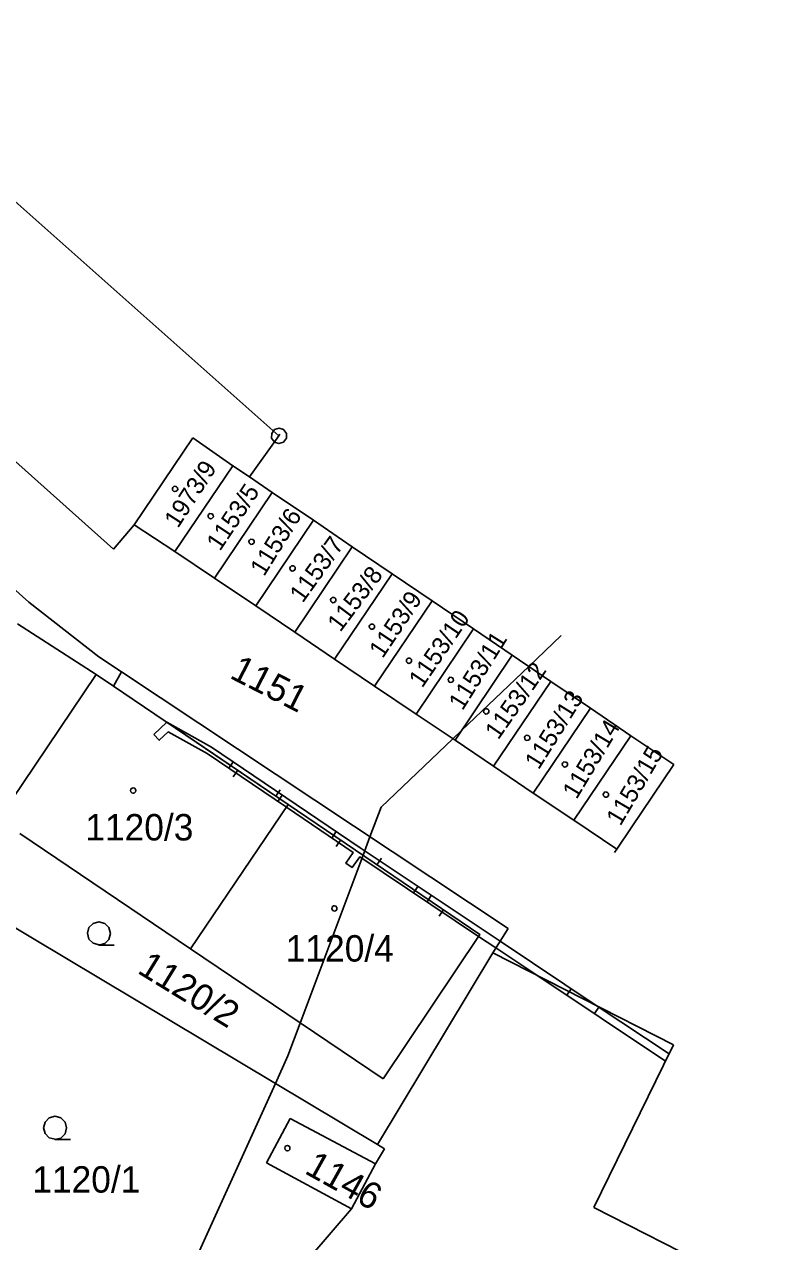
# Model space of a CAD drawing. Extents: x -806774 to -803680, y -1151731 to -1150053.
# Drawn here: x -804023.9 to -803974.9, y -1150193.4 to -1150115.2 of the extents above; entities that cross this region are included whole.
import ezdxf

# ---------------------------------------------------------------- set-up
doc = ezdxf.new("R2010")
doc.units = 0
for name, color, linetype in [('1', 7, 'Continuous'), ('11', 7, 'Continuous'), ('12', 7, 'Continuous'), ('13', 7, 'Continuous'), ('2', 7, 'Continuous'), ('3', 7, 'Continuous'), ('5', 7, 'Continuous'), ('8', 7, 'Continuous')]:
    doc.layers.add(name, color=color, linetype=linetype)

msp = doc.modelspace()

# ---------------------------------------------------------------- linework, layer by layer
at = {"layer": '1'}
for p, q in [((-804037.36, -1150115.15), (-804007.58, -1150141.61)), ((-804058.77, -1150120.88), (-804023.66, -1150152.32)), ((-804032.24, -1150136.39), (-804018.21, -1150148.91)), ((-804016.89, -1150147.33), (-804013.11, -1150141.74)), ((-804013.11, -1150141.74), (-804010.53, -1150143.54)), ((-804007.58, -1150141.61), (-804009.47, -1150144.26)), ((-804010.53, -1150143.54), (-804014.26, -1150149.06)), ((-804010.53, -1150143.54), (-804009.47, -1150144.26)), ((-804008, -1150145.26), (-804009.47, -1150144.26)), ((-804011.71, -1150150.77), (-804008, -1150145.26)), ((-804005.36, -1150147.04), (-804008, -1150145.26)), ((-804005.36, -1150147.04), (-804009.07, -1150152.55)), ((-804005.36, -1150147.04), (-804002.86, -1150148.75)), ((-804018.21, -1150148.91), (-804016.89, -1150147.33)), ((-804014.26, -1150149.06), (-804016.89, -1150147.33)), ((-804006.56, -1150154.24), (-804002.86, -1150148.75)), ((-804000.29, -1150150.49), (-804002.86, -1150148.75)), ((-804014.26, -1150149.06), (-804011.71, -1150150.77)), ((-804011.71, -1150150.77), (-804009.07, -1150152.55)), ((-804000.29, -1150150.49), (-804003.99, -1150155.98)), ((-803997.73, -1150152.23), (-804000.29, -1150150.49)), ((-804023.66, -1150152.32), (-804019.15, -1150155.82)), ((-804009.07, -1150152.55), (-804006.56, -1150154.24)), ((-804001.42, -1150157.71), (-803997.73, -1150152.23)), ((-803995.06, -1150154.03), (-803997.73, -1150152.23)), ((-804024.39, -1150153.7), (-804019.32, -1150156.96)), ((-804003.99, -1150155.98), (-804006.56, -1150154.24)), ((-803995.06, -1150154.03), (-803998.74, -1150159.51)), ((-803992.57, -1150155.73), (-803995.06, -1150154.03)), ((-804017.69, -1150156.79), (-804019.15, -1150155.82)), ((-803996.25, -1150161.19), (-803992.57, -1150155.73)), ((-803990.09, -1150157.41), (-803992.57, -1150155.73)), ((-804001.42, -1150157.71), (-804003.99, -1150155.98)), ((-804019.32, -1150156.96), (-804025.61, -1150166.26)), ((-804018.21, -1150157.71), (-804019.32, -1150156.96)), ((-804017.69, -1150156.79), (-804018.21, -1150157.71)), ((-804017.69, -1150156.79), (-803992.84, -1150173.31)), ((-804006.97, -1150165.33), (-804018.21, -1150157.71)), ((-804001.42, -1150157.71), (-803998.74, -1150159.51)), ((-803990.09, -1150157.41), (-803993.77, -1150162.87)), ((-803987.54, -1150159.14), (-803990.09, -1150157.41)), ((-803998.74, -1150159.51), (-803996.25, -1150161.19)), ((-803991.22, -1150164.59), (-803987.54, -1150159.14)), ((-803984.95, -1150160.9), (-803987.54, -1150159.14)), ((-803996.25, -1150161.19), (-803993.77, -1150162.87)), ((-803984.95, -1150160.9), (-803988.61, -1150166.34)), ((-803982.19, -1150162.76), (-803984.95, -1150160.9)), ((-803993.77, -1150162.87), (-803991.22, -1150164.59)), ((-803984.93, -1150166.82), (-803982.19, -1150162.76)), ((-803991.22, -1150164.59), (-803988.61, -1150166.34)), ((-804006.97, -1150165.33), (-804013.26, -1150174.62)), ((-803994.65, -1150173.69), (-804006.97, -1150165.33)), ((-803988.61, -1150166.34), (-803985.85, -1150168.19)), ((-804024.23, -1150167.19), (-804013.26, -1150174.62)), ((-803985.85, -1150168.19), (-803984.93, -1150166.82)), ((-803986, -1150168.42), (-803985.85, -1150168.19)), ((-804027, -1150171.78), (-804001.24, -1150187.2)), ((-804000.88, -1150182.97), (-803994.65, -1150173.69)), ((-803992.84, -1150173.31), (-803993.82, -1150174.86)), ((-804013.26, -1150174.62), (-804000.88, -1150182.97)), ((-804001.24, -1150187.2), (-803993.82, -1150174.86)), ((-803993.82, -1150174.86), (-803982.2, -1150180.79)), ((-803982.2, -1150180.79), (-803982.84, -1150182.1)), ((-803982.84, -1150182.1), (-803987.32, -1150191.24)), ((-804008.37, -1150188.37), (-804006.85, -1150185.52)), ((-804001.37, -1150188.44), (-804006.85, -1150185.52)), ((-804000.78, -1150187.47), (-804001.37, -1150188.44)), ((-804001.24, -1150187.2), (-804000.78, -1150187.47)), ((-804002.9, -1150191.34), (-804008.37, -1150188.37)), ((-804001.37, -1150188.44), (-804002.9, -1150191.34)), ((-804002.9, -1150191.34), (-804005.52, -1150194.37)), ((-803987.32, -1150191.24), (-803957.79, -1150206.26))]:
    msp.add_line(p, q, dxfattribs=at)
at = {"layer": '11'}
msp.add_lwpolyline([(-804075, -1150250.5), (-804061, -1150239.5), (-804055.76, -1150236.44), (-804047.55, -1150231.65), (-804045.03, -1150230.18), (-804037, -1150225.5), (-804030.15, -1150217.97), (-804018.95, -1150205.65), (-804018.47, -1150205.12), (-804017, -1150203.5), (-804007.8, -1150183.27), (-804007, -1150181.5), (-804006.2, -1150179.38), (-804002.16, -1150168.59), (-804001.72, -1150167.41), (-804001, -1150165.5), (-803996.39, -1150161.1), (-803995.83, -1150160.56), (-803991.51, -1150156.45), (-803989.423, -1150154.449)], dxfattribs=at)
at = {"layer": '12'}
for p, q in [((-804016.89, -1150147.33), (-804013.11, -1150141.74)), ((-804013.11, -1150141.74), (-804010.53, -1150143.54)), ((-804010.53, -1150143.54), (-804014.26, -1150149.06)), ((-804010.53, -1150143.54), (-804014.26, -1150149.06)), ((-804010.53, -1150143.54), (-804009.47, -1150144.26)), ((-804008, -1150145.26), (-804009.47, -1150144.26)), ((-804011.71, -1150150.77), (-804008, -1150145.26)), ((-804011.71, -1150150.77), (-804008, -1150145.26)), ((-804005.36, -1150147.04), (-804008, -1150145.26)), ((-804005.36, -1150147.04), (-804009.07, -1150152.55)), ((-804005.36, -1150147.04), (-804009.07, -1150152.55)), ((-804005.36, -1150147.04), (-804002.86, -1150148.75)), ((-804014.26, -1150149.06), (-804016.89, -1150147.33)), ((-804006.56, -1150154.24), (-804002.86, -1150148.75)), ((-804006.56, -1150154.24), (-804002.86, -1150148.75)), ((-804000.29, -1150150.49), (-804002.86, -1150148.75)), ((-804014.26, -1150149.06), (-804011.71, -1150150.77)), ((-804011.71, -1150150.77), (-804009.07, -1150152.55)), ((-804000.29, -1150150.49), (-804003.99, -1150155.98)), ((-804000.29, -1150150.49), (-804003.99, -1150155.98)), ((-803997.73, -1150152.23), (-804000.29, -1150150.49)), ((-804009.07, -1150152.55), (-804006.56, -1150154.24)), ((-804001.42, -1150157.71), (-803997.73, -1150152.23)), ((-804001.42, -1150157.71), (-803997.73, -1150152.23)), ((-803995.06, -1150154.03), (-803997.73, -1150152.23)), ((-804003.99, -1150155.98), (-804006.56, -1150154.24)), ((-803995.06, -1150154.03), (-803998.74, -1150159.51)), ((-803995.06, -1150154.03), (-803998.74, -1150159.51)), ((-803992.57, -1150155.73), (-803995.06, -1150154.03)), ((-803996.25, -1150161.19), (-803992.57, -1150155.73)), ((-803996.25, -1150161.19), (-803992.57, -1150155.73)), ((-803990.09, -1150157.41), (-803992.57, -1150155.73)), ((-804001.42, -1150157.71), (-804003.99, -1150155.98)), ((-804019.32, -1150156.96), (-804025.61, -1150166.26)), ((-804018.21, -1150157.71), (-804019.32, -1150156.96)), ((-804006.97, -1150165.33), (-804018.21, -1150157.71)), ((-804001.42, -1150157.71), (-803998.74, -1150159.51)), ((-803990.09, -1150157.41), (-803993.77, -1150162.87)), ((-803990.09, -1150157.41), (-803993.77, -1150162.87)), ((-803987.54, -1150159.14), (-803990.09, -1150157.41)), ((-803998.74, -1150159.51), (-803996.25, -1150161.19)), ((-803991.22, -1150164.59), (-803987.54, -1150159.14)), ((-803991.22, -1150164.59), (-803987.54, -1150159.14)), ((-803984.95, -1150160.9), (-803987.54, -1150159.14)), ((-803996.25, -1150161.19), (-803993.77, -1150162.87)), ((-803984.95, -1150160.9), (-803988.61, -1150166.34)), ((-803984.95, -1150160.9), (-803988.61, -1150166.34)), ((-803982.19, -1150162.76), (-803984.95, -1150160.9)), ((-803993.77, -1150162.87), (-803991.22, -1150164.59)), ((-803984.93, -1150166.82), (-803982.19, -1150162.76)), ((-803991.22, -1150164.59), (-803988.61, -1150166.34)), ((-803994.65, -1150173.69), (-804006.97, -1150165.33)), ((-803988.61, -1150166.34), (-803985.85, -1150168.19)), ((-804024.23, -1150167.19), (-804013.26, -1150174.62)), ((-803985.85, -1150168.19), (-803984.93, -1150166.82)), ((-804000.88, -1150182.97), (-803994.65, -1150173.69)), ((-804013.26, -1150174.62), (-804000.88, -1150182.97)), ((-804008.37, -1150188.37), (-804006.85, -1150185.52)), ((-804001.37, -1150188.44), (-804006.85, -1150185.52)), ((-804002.9, -1150191.34), (-804008.37, -1150188.37)), ((-804001.37, -1150188.44), (-804002.9, -1150191.34))]:
    msp.add_line(p, q, dxfattribs=at)
at = {"layer": '13'}
for p, q in [((-804015.62, -1150160.83), (-804014.78, -1150160.04)), ((-804014.78, -1150160.04), (-804011.92, -1150161.63)), ((-804011.92, -1150161.63), (-804002.35, -1150168.12)), ((-804010.787, -1150162.994), (-804010.507, -1150162.58)), ((-804010.226, -1150163.124), (-804010.507, -1150163.538)), ((-804007.771, -1150164.788), (-804007.49, -1150164.374)), ((-804007.368, -1150164.717), (-804007.649, -1150165.131)), ((-804004.167, -1150167.485), (-804003.886, -1150167.072)), ((-804003.605, -1150167.614), (-804003.885, -1150168.027)), ((-804002.35, -1150168.12), (-803993.35, -1150174.12)), ((-804001.27, -1150169.198), (-804000.989, -1150168.784)), ((-803998.916, -1150171.014), (-803998.639, -1150170.598)), ((-803997.774, -1150171.171), (-803998.051, -1150171.587)), ((-803996.985, -1150172.106), (-803997.266, -1150172.519)), ((-803993.62, -1150174.55), (-803994.73, -1150173.81)), ((-803990.98, -1150176.31), (-803993.62, -1150174.55)), ((-803993.35, -1150174.12), (-803987.1, -1150178.29)), ((-803982.71, -1150181.83), (-803990.98, -1150176.31)), ((-803988.775, -1150177.173), (-803989.052, -1150177.589)), ((-803987.285, -1150178.777), (-803987.007, -1150178.361)), ((-803987.1, -1150178.29), (-803982.48, -1150181.37))]:
    msp.add_line(p, q, dxfattribs=at)
for points in [[(-804014.78, -1150160.04), (-804006.97, -1150165.33), (-803994.65, -1150173.69), (-803994.73, -1150173.81), (-804002.38, -1150168.7), (-804002.87, -1150169.38), (-804003.28, -1150169.09), (-804002.79, -1150168.42), (-804007.09, -1150165.5), (-804012.18, -1150162.05), (-804014.7, -1150160.66), (-804015.27, -1150161.19), (-804015.62, -1150160.83)], [(-803994.73, -1150173.81), (-803994.65, -1150173.69), (-804006.97, -1150165.33), (-804014.78, -1150160.04)]]:
    msp.add_lwpolyline(points, dxfattribs=at)
at = {"layer": '3'}
for points in [[(-804019.14, -1150174.35), (-804019.52, -1150174.25), (-804019.79, -1150173.98), (-804019.89, -1150173.61), (-804019.79, -1150173.24), (-804019.52, -1150172.97), (-804019.15, -1150172.87), (-804018.78, -1150172.97), (-804018.51, -1150173.24), (-804018.41, -1150173.62), (-804018.51, -1150174), (-804018.78, -1150174.27), (-804019.16, -1150174.37), (-804018.16, -1150174.37)], [(-804021.96, -1150186.86), (-804022.34, -1150186.76), (-804022.61, -1150186.49), (-804022.71, -1150186.12), (-804022.61, -1150185.75), (-804022.34, -1150185.48), (-804021.97, -1150185.38), (-804021.6, -1150185.48), (-804021.33, -1150185.75), (-804021.23, -1150186.13), (-804021.33, -1150186.51), (-804021.6, -1150186.78), (-804021.98, -1150186.88), (-804020.98, -1150186.88)]]:
    msp.add_lwpolyline(points, dxfattribs=at)
at = {"layer": '5'}
for points in [[(-804014.389, -1150144.932), (-804014.315, -1150144.862), (-804014.213, -1150144.873), (-804014.152, -1150144.891), (-804014.09, -1150144.959), (-804014.079, -1150145.065), (-804014.111, -1150145.128), (-804014.187, -1150145.184), (-804014.271, -1150145.199), (-804014.348, -1150145.169), (-804014.41, -1150145.101), (-804014.421, -1150144.995)], [(-804012.099, -1150146.682), (-804012.025, -1150146.612), (-804011.923, -1150146.623), (-804011.862, -1150146.641), (-804011.8, -1150146.709), (-804011.789, -1150146.815), (-804011.821, -1150146.878), (-804011.897, -1150146.934), (-804011.981, -1150146.949), (-804012.058, -1150146.919), (-804012.12, -1150146.851), (-804012.131, -1150146.745)], [(-804009.469, -1150148.332), (-804009.395, -1150148.262), (-804009.293, -1150148.273), (-804009.232, -1150148.291), (-804009.17, -1150148.359), (-804009.159, -1150148.465), (-804009.191, -1150148.528), (-804009.267, -1150148.584), (-804009.351, -1150148.599), (-804009.428, -1150148.569), (-804009.49, -1150148.501), (-804009.501, -1150148.395)], [(-804006.839, -1150150.042), (-804006.765, -1150149.972), (-804006.663, -1150149.983), (-804006.602, -1150150.001), (-804006.54, -1150150.069), (-804006.529, -1150150.175), (-804006.561, -1150150.238), (-804006.637, -1150150.294), (-804006.721, -1150150.309), (-804006.798, -1150150.279), (-804006.86, -1150150.211), (-804006.871, -1150150.105)], [(-804004.219, -1150152.082), (-804004.145, -1150152.012), (-804004.043, -1150152.023), (-804003.982, -1150152.041), (-804003.92, -1150152.109), (-804003.909, -1150152.215), (-804003.941, -1150152.278), (-804004.017, -1150152.334), (-804004.101, -1150152.349), (-804004.178, -1150152.319), (-804004.24, -1150152.251), (-804004.251, -1150152.145)], [(-804001.729, -1150153.792), (-804001.655, -1150153.722), (-804001.553, -1150153.733), (-804001.492, -1150153.751), (-804001.43, -1150153.819), (-804001.419, -1150153.925), (-804001.451, -1150153.988), (-804001.527, -1150154.044), (-804001.611, -1150154.059), (-804001.688, -1150154.029), (-804001.75, -1150153.961), (-804001.761, -1150153.855)], [(-803999.349, -1150155.982), (-803999.275, -1150155.912), (-803999.173, -1150155.923), (-803999.112, -1150155.941), (-803999.05, -1150156.009), (-803999.039, -1150156.115), (-803999.071, -1150156.178), (-803999.147, -1150156.234), (-803999.231, -1150156.249), (-803999.308, -1150156.219), (-803999.37, -1150156.151), (-803999.381, -1150156.045)], [(-803996.659, -1150157.212), (-803996.585, -1150157.142), (-803996.483, -1150157.153), (-803996.422, -1150157.171), (-803996.36, -1150157.239), (-803996.349, -1150157.345), (-803996.381, -1150157.408), (-803996.457, -1150157.464), (-803996.541, -1150157.479), (-803996.618, -1150157.449), (-803996.68, -1150157.381), (-803996.691, -1150157.275)], [(-803994.379, -1150159.242), (-803994.305, -1150159.172), (-803994.203, -1150159.183), (-803994.142, -1150159.201), (-803994.08, -1150159.269), (-803994.069, -1150159.375), (-803994.101, -1150159.438), (-803994.177, -1150159.494), (-803994.261, -1150159.509), (-803994.338, -1150159.479), (-803994.4, -1150159.411), (-803994.411, -1150159.305)], [(-803991.749, -1150160.942), (-803991.675, -1150160.872), (-803991.573, -1150160.883), (-803991.512, -1150160.901), (-803991.45, -1150160.969), (-803991.439, -1150161.075), (-803991.471, -1150161.138), (-803991.547, -1150161.194), (-803991.631, -1150161.209), (-803991.708, -1150161.179), (-803991.77, -1150161.111), (-803991.781, -1150161.005)], [(-803989.319, -1150162.652), (-803989.245, -1150162.582), (-803989.143, -1150162.593), (-803989.082, -1150162.611), (-803989.02, -1150162.679), (-803989.009, -1150162.785), (-803989.041, -1150162.848), (-803989.117, -1150162.904), (-803989.201, -1150162.919), (-803989.278, -1150162.889), (-803989.34, -1150162.821), (-803989.351, -1150162.715)], [(-804016.95, -1150164.26), (-804016.85, -1150164.28), (-804016.8, -1150164.37), (-804016.78, -1150164.43), (-804016.8, -1150164.52), (-804016.88, -1150164.59), (-804016.95, -1150164.6), (-804017.04, -1150164.57), (-804017.1, -1150164.51), (-804017.12, -1150164.43), (-804017.1, -1150164.34), (-804017.02, -1150164.27)], [(-803986.689, -1150164.592), (-803986.615, -1150164.522), (-803986.513, -1150164.533), (-803986.452, -1150164.551), (-803986.39, -1150164.619), (-803986.379, -1150164.725), (-803986.411, -1150164.788), (-803986.487, -1150164.844), (-803986.571, -1150164.859), (-803986.648, -1150164.829), (-803986.71, -1150164.761), (-803986.721, -1150164.655)], [(-804004.01, -1150171.84), (-804003.91, -1150171.86), (-804003.86, -1150171.95), (-804003.84, -1150172.01), (-804003.86, -1150172.1), (-804003.94, -1150172.17), (-804004.01, -1150172.18), (-804004.1, -1150172.15), (-804004.16, -1150172.09), (-804004.18, -1150172.01), (-804004.16, -1150171.92), (-804004.08, -1150171.85)], [(-804006.953, -1150187.279), (-804006.873, -1150187.342), (-804006.869, -1150187.445), (-804006.879, -1150187.507), (-804006.937, -1150187.578), (-804007.04, -1150187.604), (-804007.107, -1150187.581), (-804007.174, -1150187.514), (-804007.2, -1150187.433), (-804007.181, -1150187.353), (-804007.123, -1150187.282), (-804007.02, -1150187.256)]]:
    msp.add_lwpolyline(points, close=True, dxfattribs=at)
at = {"layer": '8'}
msp.add_line((-804007.509, -1150141.513), (-804007.651, -1150141.707), dxfattribs=at)
msp.add_lwpolyline([(-804007.282, -1150142.015), (-804007.575, -1150142.11), (-804007.868, -1150142.019), (-804008.042, -1150141.767), (-804008.04, -1150141.459), (-804007.856, -1150141.209), (-804007.563, -1150141.114), (-804007.27, -1150141.205), (-804007.096, -1150141.457), (-804007.098, -1150141.765)], close=True, dxfattribs=at)

# ---------------------------------------------------------------- texts
at = {"layer": '2'}
for s, height, rotation, p in [('1973/9', 1.14, 57.12389, (-804014.067, -1150147.609)), ('1153/5', 1.14, 56.32175, (-804011.364, -1150149.081)), ('1153/6', 1.14, 58.15522, (-804008.531, -1150150.706)), ('1153/7', 1.14, 54.48829, (-804006.047, -1150152.416)), ('1153/8', 1.14, 53.11319, (-804003.632, -1150154.289)), ('1153/9', 1.14, 56.32175, (-804000.904, -1150155.981)), ('1153/10', 1.14, 55.6915, (-803998.362, -1150157.882)), ('1153/11', 1.14, 57.98333, (-803995.77, -1150159.337)), ('1151', 1.7, 333.00307, (-804010.809, -1150157.159)), ('1153/12', 1.14, 55.11854, (-803993.469, -1150161.214)), ('1153/13', 1.14, 57.98333, (-803990.87, -1150163.137)), ('1153/14', 1.14, 59.01465, (-803988.434, -1150165.044)), ('1153/15', 1.14, 59.53031, (-803985.616, -1150166.763)), ('1120/2', 1.7, 328.4767, (-804016.745, -1150176.125)), ('1146', 1.7, 330.82583, (-804005.997, -1150189.011))]:
    msp.add_text(s, height=height, rotation=rotation, dxfattribs=at).set_placement(p)
for s, p in [('1120/3', (-804020.027, -1150167.64)), ('1120/4', (-804007.137, -1150175.43)), ('1120/1', (-804023.437, -1150190.29))]:
    msp.add_text(s, height=1.7, dxfattribs=at).set_placement(p)

doc.saveas('drawing.dxf')
